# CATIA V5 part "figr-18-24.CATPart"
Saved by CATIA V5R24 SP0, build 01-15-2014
Part number: Part1
Bounding box of the stored display mesh (mm): x 0 to 100, y -127 to 127, z -16 to 0
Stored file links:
  D:\KAVITA\CATIA V5-6R2014 Project_ Kavita\CATIA V5-6R2014_partfiles\Partfiles\c17_caia_v6-6r2014_prt\figr-17-24.CATPart
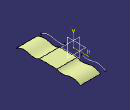
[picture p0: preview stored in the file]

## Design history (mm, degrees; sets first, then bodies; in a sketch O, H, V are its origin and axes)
Body1 (main body)
  Sketch1 on yz-plane, origin (0, 0, 0), H (0, 1, 0), V (0, 0, 1)
    spline S1 through (-127, -16) (-75, -8) (-52.8201, -11.5937) (-35, -5.5937)
    spline S2 through (127, -16) (75, -8) (52.8201, -11.5937) (35, -5.5937)
    point P1 (-35, -5.5937)
    point P2 (35, -5.5937)
    point P3 (-127, -16)
    point P4 (127, -16)
    point P5 (-52.8201, -11.5937)
    point P6 (52.8201, -11.5937)
    point P7 (-75, -8)
    point P8 (75, -8)
    symmetry: S1 S2 V, P1 P2 V, P3 P4 V, P5 P6 V, P7 P8 V
  Extrude1: Lim1 20, Lim2 -100, Element1 Sketch1
  DatumSurface1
